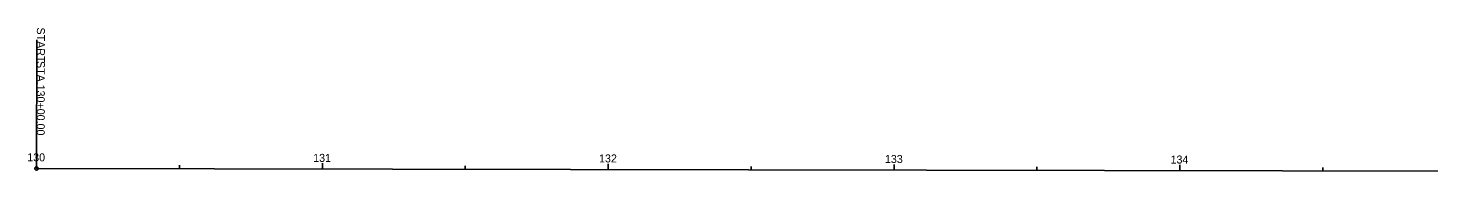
# Model space of a CAD drawing. Extents: x 1501024 to 1508874, y 327839 to 328839.
# Drawn here: x 1501024.5 to 1501514.6, y 328450.2 to 328501.7 of the extents above; entities that cross this region are included whole.
import ezdxf

# ---------------------------------------------------------------- set-up
doc = ezdxf.new("R2010")
doc.units = 0
for name, color, linetype in [('GE_X_Alignment', 7, 'Continuous'), ('GE_X_Alignment_100_Cardinal_Points', 7, 'Continuous'), ('GE_X_Alignment_100_Stations', 7, 'Continuous'), ('GE_X_Alignment_500_Cardinal_Points', 7, 'Continuous'), ('GE_X_Alignment_500_Stations', 7, 'Continuous')]:
    doc.layers.add(name, color=color, linetype=linetype)

msp = doc.modelspace()

# ---------------------------------------------------------------- linework, layer by layer
at = {"layer": 'GE_X_Alignment'}
msp.add_line((1501027.44, 328452.53), (1502212.06, 328450.23), dxfattribs=at)
at = {"layer": 'GE_X_Alignment_100_Cardinal_Points'}
msp.add_line((1501027.44, 328452.53), (1501027.53, 328497.53), dxfattribs=at)
msp.add_circle((1501027.44, 328452.53), 0.6, dxfattribs=at)
at = {"layer": 'GE_X_Alignment_100_Stations'}
for p, q in [((1501027.44, 328452.53), (1501027.45, 328454.53)), ((1501077.44, 328452.43), (1501077.44, 328453.63)), ((1501127.44, 328452.33), (1501127.45, 328454.33)), ((1501177.44, 328452.24), (1501177.44, 328453.44)), ((1501227.44, 328452.14), (1501227.45, 328454.14)), ((1501277.44, 328452.04), (1501277.44, 328453.24)), ((1501327.44, 328451.95), (1501327.45, 328453.95)), ((1501377.44, 328451.85), (1501377.44, 328453.05)), ((1501427.44, 328451.75), (1501427.44, 328453.75)), ((1501477.44, 328451.66), (1501477.44, 328452.86))]:
    msp.add_line(p, q, dxfattribs=at)
at = {"layer": 'GE_X_Alignment_500_Cardinal_Points'}
msp.add_line((1501027.44, 328452.53), (1501027.53, 328497.53), dxfattribs=at)
msp.add_circle((1501027.44, 328452.53), 0.6, dxfattribs=at)
at = {"layer": 'GE_X_Alignment_500_Stations'}
for p, q in [((1501027.44, 328452.53), (1501027.45, 328454.53)), ((1501127.44, 328452.33), (1501127.44, 328453.53)), ((1501227.44, 328452.14), (1501227.44, 328453.34)), ((1501327.44, 328451.95), (1501327.44, 328453.15)), ((1501427.44, 328451.75), (1501427.44, 328452.95))]:
    msp.add_line(p, q, dxfattribs=at)

# ---------------------------------------------------------------- texts
at = {"layer": 'GE_X_Alignment_100_Cardinal_Points'}
for s, p in [('START', (1501027.57, 328501.91)), (' STA. ', (1501027.55, 328491.22)), ('130+00.00', (1501027.54, 328481.9))]:
    msp.add_text(s, height=2.8, rotation=269.889, dxfattribs=at).set_placement(p)
at = {"layer": 'GE_X_Alignment_100_Stations'}
for s, p in [('130', (1501024.18, 328455.03)), ('131', (1501124.22, 328454.84)), ('132', (1501224.23, 328454.65)), ('133', (1501324.25, 328454.45)), ('134', (1501424.17, 328454.26))]:
    msp.add_text(s, height=2.8, rotation=359.889, dxfattribs=at).set_placement(p)
at = {"layer": 'GE_X_Alignment_500_Cardinal_Points'}
for s, p in [('START', (1501027.57, 328501.91)), (' STA. ', (1501027.55, 328491.22)), ('130+00.00', (1501027.54, 328481.9))]:
    msp.add_text(s, height=2.8, rotation=269.889, dxfattribs=at).set_placement(p)
at = {"layer": 'GE_X_Alignment_500_Stations'}
msp.add_text('130', height=2.8, rotation=359.889, dxfattribs=at).set_placement((1501024.18, 328455.03))

doc.saveas('drawing.dxf')
